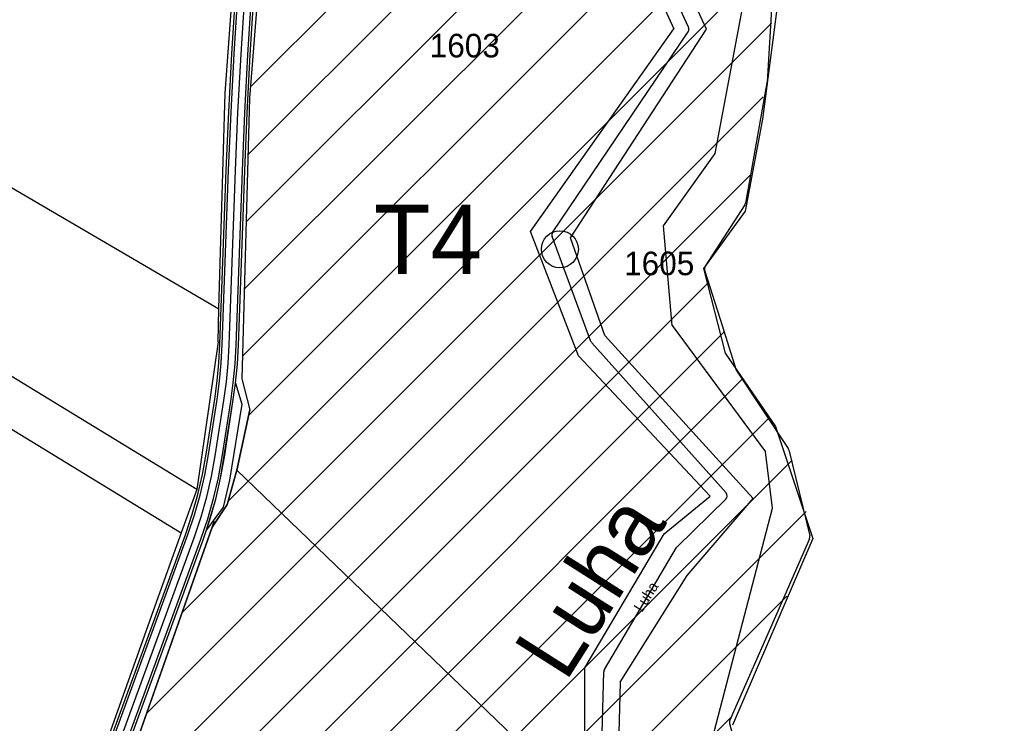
# Model space of a CAD drawing. Extents: x -510185 to -506993, y -1126306 to -1123642.
# Drawn here: x -508848.9 to -508636.4, y -1124742.5 to -1124590.2 of the extents above; entities that cross this region are included whole.
import ezdxf

# ---------------------------------------------------------------- set-up
doc = ezdxf.new("R2010")
doc.units = 0
for name, color, linetype in [('parcelni hranice', 7, 'Continuous'), ('tunky', 7, 'Continuous'), ('u_cesta45', 7, 'Continuous'), ('u_osa45', 7, 'Continuous'), ('u_popis', 7, 'Continuous'), ('u_stávající', 7, 'Continuous'), ('u_tok Luha', 7, 'Continuous'), ('u_vysadba', 7, 'Continuous'), ('x_rozsireni cesty', 7, 'Continuous'), ('ˇ2', 7, 'Continuous'), ('ˇ7', 7, 'Continuous')]:
    doc.layers.add(name, color=color, linetype=linetype)

msp = doc.modelspace()

# ---------------------------------------------------------------- linework, layer by layer
at = {"layer": 'parcelni hranice'}
for p, q in [((-508804.4, -1124606.05), (-508798.99, -1124530.02)), ((-508700.22, -1124592.21), (-508715.23, -1124560.27)), ((-508720.08, -1124564.37), (-508707.3, -1124592.14)), ((-508796.15, -1124569.25), (-508799.15, -1124607.15)), ((-508698.4, -1124619.11), (-508691.12, -1124580.58)), ((-508909.1, -1124592.5), (-508805.75, -1124652.78)), ((-508738.36, -1124636.01), (-508707.3, -1124592.14)), ((-508729.66, -1124637.37), (-508700.22, -1124592.21)), ((-508805.75, -1124652.78), (-508804.4, -1124606.05)), ((-508799.15, -1124607.15), (-508800.8, -1124667.9)), ((-508709.58, -1124634.78), (-508698.4, -1124619.11)), ((-508810.51, -1124691.87), (-508921.82, -1124623.94)), ((-508926.77, -1124632.36), (-508813.91, -1124701.25)), ((-508707.65, -1124656.33), (-508709.58, -1124634.78)), ((-508727.96, -1124662.9), (-508738.36, -1124636.01)), ((-508722.23, -1124658.55), (-508729.66, -1124637.37)), ((-508805.95, -1124659.93), (-508805.75, -1124652.78)), ((-508707.65, -1124656.33), (-508687.48, -1124683.7)), ((-508690.12, -1124693.79), (-508722.23, -1124658.55)), ((-508805.95, -1124659.93), (-508810.51, -1124691.87)), ((-508699.48, -1124693.33), (-508727.96, -1124662.9)), ((-508800.8, -1124667.9), (-508799.1, -1124674.61)), ((-508799.1, -1124674.61), (-508801.86, -1124687.67)), ((-508685.93, -1124695.92), (-508687.48, -1124683.7)), ((-508801.86, -1124687.67), (-508803.98, -1124695.09)), ((-508801.86, -1124687.67), (-508726.64, -1124760.11)), ((-508810.51, -1124691.87), (-508813.91, -1124701.25)), ((-508803.98, -1124695.09), (-508807.26, -1124699.99)), ((-508709.39, -1124701.48), (-508699.48, -1124693.33)), ((-508704.41, -1124710.44), (-508690.12, -1124693.79)), ((-508700.29, -1124750.72), (-508685.93, -1124695.92)), ((-508807.26, -1124699.99), (-508838.66, -1124789.41)), ((-508813.91, -1124701.25), (-508819.64, -1124717.08)), ((-508726.57, -1124730.43), (-508709.39, -1124701.48)), ((-508718.91, -1124733.58), (-508704.41, -1124710.44)), ((-508819.64, -1124717.08), (-508843.22, -1124783.6)), ((-508726.64, -1124760.11), (-508726.57, -1124730.43)), ((-508718.91, -1124733.58), (-508719.91, -1124768.57))]:
    msp.add_line(p, q, dxfattribs=at)
at = {"layer": 'tunky'}
msp.add_circle((-508731.98, -1124639.88), 4, dxfattribs=at)
msp.add_circle((-508731.98, -1124639.88), 4, dxfattribs=at)
at = {"layer": 'u_cesta45'}
for points in [[(-508840.46, -1124776.68), (-508812.95, -1124701.42), (-508811.53, -1124697.2), (-508810.32, -1124692.94), (-508809.32, -1124688.62), (-508808.53, -1124684.23), (-508806.68, -1124672.29), (-508806.15, -1124668.35), (-508805.77, -1124664.41), (-508805.55, -1124660.44), (-508804.17, -1124622.73), (-508803.64, -1124610.15), (-508802.98, -1124597.56), (-508802.18, -1124584.99)], [(-508839.98, -1124776.84), (-508812.48, -1124701.59), (-508811.05, -1124697.35), (-508809.83, -1124693.06), (-508808.83, -1124688.72), (-508808.03, -1124684.31), (-508806.18, -1124672.36), (-508805.65, -1124668.41), (-508805.27, -1124664.45), (-508805.05, -1124660.46), (-508803.67, -1124622.75), (-508803.14, -1124610.17), (-508802.48, -1124597.59), (-508801.68, -1124585.02)], [(-508837.14, -1124777.8), (-508809.65, -1124702.59), (-508808.18, -1124698.24), (-508806.93, -1124693.81), (-508805.89, -1124689.32), (-508805.07, -1124684.81), (-508803.22, -1124672.79), (-508802.67, -1124668.75), (-508802.28, -1124664.67), (-508802.05, -1124660.6), (-508800.67, -1124622.87), (-508800.15, -1124610.31), (-508799.49, -1124597.77), (-508798.69, -1124585.22)], [(-508836.67, -1124777.96), (-508809.18, -1124702.75), (-508807.71, -1124698.39), (-508806.44, -1124693.93), (-508805.4, -1124689.42), (-508804.58, -1124684.89), (-508802.72, -1124672.87), (-508802.17, -1124668.81), (-508801.78, -1124664.71), (-508801.55, -1124660.62), (-508800.17, -1124622.89), (-508799.65, -1124610.34), (-508798.99, -1124597.79), (-508798.19, -1124585.26)]]:
    msp.add_lwpolyline(points, dxfattribs=at)
at = {"layer": 'u_osa45'}
msp.add_lwpolyline([(-508838.56, -1124777.32), (-508811.07, -1124702.09), (-508809.62, -1124697.8), (-508808.38, -1124693.44), (-508807.36, -1124689.02), (-508806.55, -1124684.56), (-508804.7, -1124672.58), (-508804.16, -1124668.58), (-508803.78, -1124664.56), (-508803.55, -1124660.53), (-508802.17, -1124622.81), (-508801.65, -1124610.24), (-508800.98, -1124597.68), (-508800.19, -1124585.12)], dxfattribs=at)
at = {"layer": 'u_stávající'}
for p, q in [((-508798.96, -1124604.75), (-508637.46, -1124443.24)), ((-508799.48, -1124619.41), (-508628.78, -1124448.71)), ((-508799.88, -1124633.95), (-508691.77, -1124525.84)), ((-508800.27, -1124648.49), (-508691.42, -1124539.63)), ((-508800.67, -1124663.02), (-508690.61, -1124552.96)), ((-508799.41, -1124675.91), (-508689.61, -1124566.11)), ((-508796.15, -1124569.25), (-508799.15, -1124607.15)), ((-508803.83, -1124694.47), (-508686.35, -1124576.99)), ((-508685.79, -1124580.95), (-508687.14, -1124603.73)), ((-508813.79, -1124718.57), (-508686.17, -1124590.96)), ((-508687.15, -1124603.85), (-508691.78, -1124629.89)), ((-508821.42, -1124740.35), (-508687.96, -1124606.89)), ((-508799.15, -1124607.15), (-508800.8, -1124667.9)), ((-508829.09, -1124762.15), (-508690.79, -1124623.85)), ((-508691.93, -1124630.26), (-508700.52, -1124643.53)), ((-508836.74, -1124783.95), (-508699.97, -1124647.18)), ((-508833.86, -1124795.21), (-508696.47, -1124657.82)), ((-508693.69, -1124666.26), (-508682.56, -1124682.95)), ((-508827.46, -1124802.95), (-508692.52, -1124668.01)), ((-508800.8, -1124667.9), (-508799.1, -1124674.61)), ((-508821.05, -1124810.69), (-508686.76, -1124676.4)), ((-508682.42, -1124683.26), (-508677.87, -1124701.86)), ((-508814.47, -1124818.25), (-508681.73, -1124685.5)), ((-508808.25, -1124826.16), (-508678.68, -1124696.6)), ((-508801.57, -1124833.63), (-508682.87, -1124714.93)), ((-508822.96, -1124744.7), (-508819.51, -1124734.91)), ((-508794.87, -1124841.07), (-508694.76, -1124740.96))]:
    msp.add_line(p, q, dxfattribs=at)
for points in [[(-508700.64, -1124644.38), (-508697.27, -1124655.03), (-508693.81, -1124666)], [(-508803.94, -1124694.92), (-508801.86, -1124687.67), (-508799.1, -1124674.61)], [(-508819.51, -1124734.91), (-508807.26, -1124699.99), (-508804.08, -1124695.24)], [(-508677.92, -1124702.5), (-508684.8, -1124718.17), (-508695.18, -1124741.81)], [(-508695.23, -1124742.47), (-508686.36, -1124775.45), (-508677.45, -1124808.6)]]:
    msp.add_lwpolyline(points, dxfattribs=at)
for centre, start, end in [((-508688.14, -1124603.67), 349.9194, 356.6051), ((-508692.77, -1124629.72), 327.0613, 349.9194), ((-508699.69, -1124644.08), 147.0613, 197.5256), ((-508692.86, -1124665.7), 197.5256, 213.6901), ((-508683.39, -1124683.5), 13.7608, 33.6901), ((-508804.91, -1124694.68), 326.2021, 346.5974), ((-508678.84, -1124702.1), 336.2974, 13.7608), ((-508694.27, -1124742.21), 156.2974, 195.0519)]:
    msp.add_arc(centre, 1, start, end, dxfattribs=at)
at = {"layer": 'u_tok Luha'}
for p, q in [((-508704.13, -1124591.8), (-508717.86, -1124561.82)), ((-508733.55, -1124636.22), (-508704.21, -1124592.78)), ((-508725.24, -1124659.81), (-508733.66, -1124637.13)), ((-508696.02, -1124692.59), (-508725.05, -1124660.13)), ((-508706.59, -1124704.23), (-508696.07, -1124693.98)), ((-508722.33, -1124730.81), (-508706.75, -1124704.43)), ((-508723.48, -1124768.27), (-508722.47, -1124731.29))]:
    msp.add_line(p, q, dxfattribs=at)
for centre, start, end in [((-508705.04, -1124592.22), 325.9611, 24.6094), ((-508732.72, -1124636.78), 145.9611, 200.3583), ((-508724.31, -1124659.46), 200.3583, 221.8054), ((-508696.76, -1124693.26), 314.2462, 41.8054), ((-508705.89, -1124704.94), 134.2462, 149.4314), ((-508721.47, -1124731.32), 149.4314, 178.4368)]:
    msp.add_arc(centre, 1, start, end, dxfattribs=at)
at = {"layer": 'u_vysadba'}
for p, q in [((-508799.1, -1124674.61), (-508801.86, -1124687.67)), ((-508801.86, -1124687.67), (-508803.98, -1124695.09)), ((-508803.98, -1124695.09), (-508807.26, -1124699.99)), ((-508807.26, -1124699.99), (-508838.66, -1124789.41))]:
    msp.add_line(p, q, dxfattribs=at)
msp.add_lwpolyline([(-508615.42, -1124493.96), (-508642.14, -1124523.17), (-508653.33, -1124532.8), (-508659.85, -1124539.64), (-508667, -1124543.99), (-508674.45, -1124539.33), (-508682.53, -1124529.38), (-508691.86, -1124535.6), (-508689.68, -1124562.63), (-508686.57, -1124577.86), (-508684.71, -1124585.62), (-508688.13, -1124611.72), (-508691.86, -1124631.61), (-508700.87, -1124644.04), (-508696.21, -1124662.37), (-508685.33, -1124678.22), (-508677.25, -1124702.46), (-508694.65, -1124742.85)], dxfattribs=at)
msp.add_lwpolyline([(-508827.62, -1124949.9), (-508816.5, -1124937.64), (-508797.97, -1124933.37), (-508794.55, -1124929.09), (-508797.4, -1124906.29), (-508792.56, -1124892.6), (-508792.56, -1124887.19), (-508798.83, -1124885.76), (-508810.23, -1124876.92), (-508817.64, -1124866.95), (-508819.35, -1124857.82), (-508815.65, -1124849.84), (-508797.12, -1124848.42), (-508790.28, -1124852.12), (-508796.26, -1124841.01), (-508838.66, -1124789.41), (-508806.81, -1124698.75), (-508838.74, -1124789.41), (-508836.46, -1124827.61), (-508835.6, -1124843.29), (-508824.77, -1124873.22), (-508819.92, -1124896.02), (-508821.06, -1124920.26)], close=True, dxfattribs=at)
at = {"layer": 'x_rozsireni cesty'}
msp.add_lwpolyline([(-508802.17, -1124668.81), (-508800.78, -1124673.41), (-508803.44, -1124689.83), (-508804.86, -1124695.69), (-508808.44, -1124700.57), (-508806.44, -1124693.93), (-508805.4, -1124689.42), (-508802.72, -1124672.87)], close=True, dxfattribs=at)

# ---------------------------------------------------------------- texts
at = {"layer": 'u_popis'}
msp.add_text('T4', height=15, dxfattribs=at).set_placement((-508772.21, -1124645.25))
at = {"layer": 'u_tok Luha'}
msp.add_text('Luha', height=13.8, rotation=57.5823, dxfattribs=at).set_placement((-508730.72, -1124733.71))
at = {"layer": 'ˇ2'}
for s, p in [('1603', (-508760.14, -1124598.34)), ('1605', (-508718.06, -1124645.48))]:
    msp.add_text(s, height=5.1, dxfattribs=at).set_placement(p)
at = {"layer": 'ˇ7'}
msp.add_text('Luha', height=2.3, rotation=57.5823, dxfattribs=at).set_placement((-508714.19, -1124718.55))

doc.saveas('drawing.dxf')
